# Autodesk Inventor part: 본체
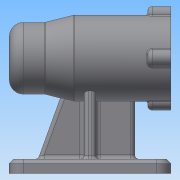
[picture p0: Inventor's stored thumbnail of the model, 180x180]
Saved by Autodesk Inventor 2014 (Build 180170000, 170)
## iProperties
Created: 2019-07
Part Number: 본체
Material: 일반
Document SubType Name: Modeling
Designer: net
Density: 1 g/cm^3
Appearance: 기본값
Author: net
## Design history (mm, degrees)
sketch "스케치1"
  geometry: L1 (-56, 0)-(56, 0); L2 (56, 30)-(-11, 30); L3 (-11, 30)-(-31, 25); L4 (-31, 25)-(-56, 25); L5 (56, 30)-(56, 21); L6 (56, 21)-(41, 21); L7 (41, 21)-(41, 24); L8 (41, 24)-(-13, 24); L9 (-13, 24)-(-13, 21); L10 (-13, 21)-(-25, 21); L11 (-25, 21)-(-25, 17.5); L12 (-25, 17.5)-(-43, 17.5); L13 (-43, 17.5)-(-43, 16); L14 (-43, 16)-(-47, 16); L15 (-47, 16)-(-47, 10.5); L16 (-47, 10.5)-(-50, 10.5); L17 (-50, 10.5)-(-50, 0); L18 (-56, 25)-(-56, 0); L19 (-50, 0)-(-56, 0); 2 further points
  constraints: 38 end point, 10 parallel, 6 perpendicular, 2 coincident, 2 vertical alignment, 1 collinear, 1 horizontal, 1 midpoint, 1 point on line
  dimensions: "d0" = 112 distance of L1.start L1.end; "d1" = 15 distance of L5.end L6.end; "d2" = 48 diameter of L8 L1; "d3" = 42 diameter of L10 L1; "d4" = 25 distance of L3.end L4.end; "d5" = 45 horizontal distance of L2.end L4.end; "d6" = 35 diameter of L12 L1; "d7" = 32 diameter of L14 L1; "d8" = 21 diameter of L16 L1; "d9" = 18 distance of L11.end L12.end; "d10" = 12 distance of L9.end L10.end; "d11" = 54 distance of L7.end L8.end; "d12" = 3 distance of L15.end L16.end; "d13" = 60 diameter of L2.end L1; "d14" = 50 diameter of L4.end L1; "d15" = 42 diameter of L5.end L1; "d69" = 4 distance of L13.end L14.end
revolve "회전1" sketch "스케치1" stored, may be unused: angle "d16" = 90 deg
sketch "스케치2"
  geometry: C1 r 6 at (-30, 0); C2 r 6 at (0, -30); C3 r 6 at (30, 0); C4 r 6 at (0, 30); A1 r 30 centre (0, 0) between (-30, 0) and (0, -30) reference
  constraints: 4 centre point, 4 point on circle
  dimensions: "d17" = 12 diameter of C1; "d18" = 12 diameter of C2; "d19" = 12 diameter of C3; "d20" = 12 diameter of C4
extrude "돌출1" join sketch "스케치2" distance "d21" = 16; taper "d22" = 0 deg
sketch "스케치3"
  geometry: A1 r 6 centre (0, 0) between (0.6, 5.97) and (0.6, -5.97) reference; A2 r 6 centre (30, -30) between (24.03, -29.4) and (35.97, -29.4) reference; A3 r 6 centre (60, 0) between (59.4, -5.97) and (59.4, 5.97) reference; A4 r 6 centre (30, 30) between (35.97, 29.4) and (24.03, 29.4) reference; 4 further points
  constraints: 4 coincident
hole "구멍1" sketch "스케치3" at (30, 30), (60, 0), (30, -30), (0, 0) diameter "d23" = 3.242; stored, may be unused: countersink angle "d27" = 90 deg, drill point angle "d29" = 118 deg; dims "d24" = 8, "d25" = 4, "d26" = 2, "d28" = 11
fillet "모깎기2" dims "d31" = 0.3
fillet "모깎기3" dims "d32" = 3
node "작업 평면1"
sketch "스케치4"
  geometry: L1 (-56, -35)-(56, -35); L2 (56, -35)-(56, 35); L3 (56, 35)-(-56, 35); L4 (-56, 35)-(-56, -35); L5 (-56, -35)-(56, 35); L6 (56, -35)-(-56, 35); 1 further point
  constraints: 12 end point, 2 midpoint, 2 parallel, 1 horizontal, 1 perpendicular
  dimensions: "d34" = 112 distance of L2.end L3.end; "d35" = 70 distance of L1.end L2.end
extrude "돌출2" join sketch "스케치4" distance "d36" = 10; taper "d37" = 0 deg
fillet "모깎기4" dims "d38" = 10
sketch "스케치5"
  geometry: C1 r 3 at (46, -25); C2 r 3 at (-46, -25); C3 r 3 at (-46, 25); C4 r 3 at (46, 25); A1 r 10 centre (-46, 25) between (-46, 35) and (-56, 25) reference; A2 r 10 centre (-46, -25) between (-56, -25) and (-46, -35) reference; A3 r 10 centre (46, -25) between (46, -35) and (56, -25) reference; A4 r 10 centre (46, 25) between (56, 25) and (46, 35) reference; 1 further point
  constraints: 4 centre point, 4 coincident
  dimensions: "d39" = 6 diameter of C1; "d40" = 6 diameter of C2; "d41" = 6 diameter of C3; "d42" = 6 diameter of C4
extrude "돌출3" cut sketch "스케치5" distance "d43" = 10; taper "d44" = 0 deg
sketch "스케치7"
  geometry: L1 (46, -70)-(-46, -70) reference; L2 (56, -80)-(56, -70) reference; L3 (-56, -70)-(-56, -80) reference; L4 (36, -70)-(19.742, -25.332); L5 (19.742, -25.332)-(-31, -25.332); L6 (-31, -25.332)-(-31, -70); L7 (36, -70)-(-31, -70); 3 further points
  constraints: 8 end point, 3 perpendicular, 2 point on line
  dimensions: "d49" = 20 distance from line of L2 L4.start; "d50" = 25 distance from line of L3 L6.end; "d51" = 110 deg angle of L1 L4
extrude "돌출4" join sketch "스케치7" stored distance "d52" = 8; taper "d53" = 0 deg
sketch "스케치8"
  geometry: L1 (35, -70)-(35, -80) reference; L2 (-35, -80)-(-35, -70) reference; L3 (-25, -70)-(25, -70) reference; L4 (25, -70)-(32, -70) reference; L5 (-32, -70)-(-25, -70) reference; L6 (28, -70)-(19.139, -19.747); L7 (-28, -70)-(-19.139, -19.747); L8 (28, -70)-(-28, -70); A1 r 27.5 centre (0, 0) between (-19.139, -19.747) and (19.139, -19.747); 3 further points
  constraints: 6 end point, 2 point on circle, 2 point on line, 1 centre point, 1 coincident, 1 collinear
  dimensions: "d56" = 7 horizontal distance of L1.end L6.start; "d57" = 7 horizontal distance of L2.start L7.start
extrude "돌출5" join sketch "스케치8" stored distance "d60" = 8; taper "d61" = 0 deg
fillet "모깎기6" dims "d62" = 3
fillet "모깎기7" dims "d63" = 3
chamfer "모따기1" distance "d64" = 3; stored, may be unused: second distance "d65" = 2, angle "d66" = 45 deg
fillet "모깎기8" dims "d67" = 10
fillet "모깎기9" dims "d68" = 3
fillet "모깎기10" dims "d70" = 1
fillet "모깎기11" dims "d71" = 3
chamfer "모따기2" distance "d72" = 1; stored, may be unused: second distance "d73" = 2, angle "d74" = 45 deg
node "솔리드1"
other parameters: "d54" = 55, "d58" = 100 deg, "d59" = 100 deg
